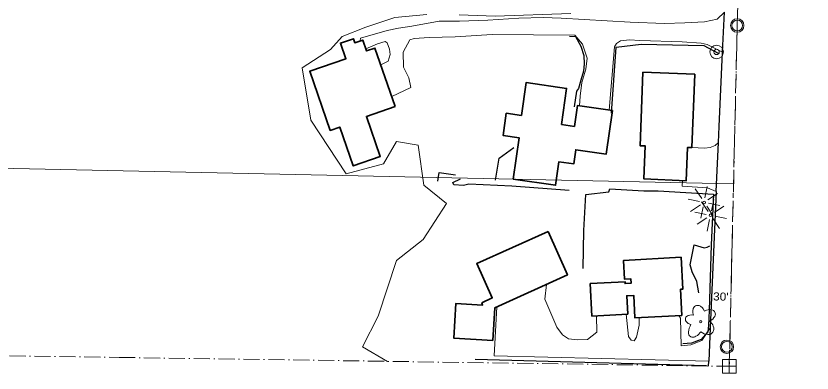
# Model space of a CAD drawing. Extents: x -861682 to -858969, y -1797841 to -1795153.
# Drawn here: x -859566 to -858974, y -1797841 to -1797576 of the extents above; entities that cross this region are included whole.
import ezdxf

# ---------------------------------------------------------------- set-up
doc = ezdxf.new("R2010")
doc.units = 0
doc.header["$LTSCALE"] = 2.4
doc.linetypes.add('DOT_DASHED', pattern=[7.7, 5, -1.2, 0.3, -1.2])
doc.linetypes.add('LONG_DASH_SHORT_DASH', pattern=[9.9, 6, -1.2, 1.5, -1.2])
for name, color, linetype, lineweight in [('10', 7, 'Continuous', 25), ('11', 7, 'Continuous', 13), ('12', 7, 'Continuous', 35), ('14', 7, 'Continuous', 25), ('17', 7, 'Continuous', 13), ('18', 7, 'Continuous', 13), ('30', 7, 'Continuous', 13), ('31', 7, 'Continuous', 13), ('32', 7, 'LONG_DASH_SHORT_DASH', 13), ('36', 7, 'Continuous', 13), ('61', 7, 'Continuous', 13)]:
    doc.layers.add(name, color=color, linetype=linetype, lineweight=lineweight)
doc.layers.add('43', color=7, linetype='Continuous')

msp = doc.modelspace()

# ---------------------------------------------------------------- linework, layer by layer
at = {"layer": '10'}
for p, q in [((-859040.841, -1797602.889), (-859039.445, -1797573.069)), ((-859045.551, -1797706.269), (-859043.943, -1797669.848)), ((-859045.551, -1797706.269), (-859050.013, -1797807.357)), ((-859050.013, -1797807.357), (-859051.105, -1797832.086)), ((-859051.263, -1797835.658), (-859051.105, -1797832.086))]:
    msp.add_line(p, q, dxfattribs=at)
msp.add_lwpolyline([(-859043.943, -1797669.848), (-859043.423, -1797658.051), (-859040.841, -1797602.889)], dxfattribs=at)
at = {"layer": '11'}
for points in [[(-859309.938, -1797594.48), (-859309.62, -1797592.433), (-859289.953, -1797586.603), (-859281.507, -1797585.021), (-859271.667, -1797583.556), (-859251.167, -1797579.721), (-859236.104, -1797579.853), (-859215.218, -1797579.069), (-859192.063, -1797577.66), (-859174.024, -1797577.051), (-859160.73, -1797577.456), (-859109.405, -1797580.619), (-859083.978, -1797581.644), (-859068.807, -1797581.049), (-859054.386, -1797580.217), (-859044.812, -1797578.418), (-859039.445, -1797573.069)], [(-859147.113, -1797642.612), (-859146.722, -1797635.543), (-859145.323, -1797625.243), (-859142.423, -1797615.417), (-859141.468, -1797607.159), (-859144.975, -1797596.843), (-859150.527, -1797590.256), (-859212.015, -1797589.653), (-859239.524, -1797591.399), (-859258.797, -1797591.869), (-859269.741, -1797592.628), (-859273.122, -1797593.726), (-859278.086, -1797602.915), (-859277.739, -1797613.833), (-859273.798, -1797621.755), (-859272.425, -1797628.945), (-859286.527, -1797635.627)], [(-859125.138, -1797645.75), (-859121.079, -1797598.921), (-859119.617, -1797596.398), (-859116.758, -1797594.472), (-859109.954, -1797593.68), (-859102.239, -1797594.124), (-859070.757, -1797595.108), (-859056.83, -1797596.093), (-859052.273, -1797597.107), (-859040.841, -1797602.889)], [(-859294.688, -1797612.104), (-859289.062, -1797609.376), (-859287.679, -1797604.522), (-859288.066, -1797600.452), (-859289.911, -1797595.75), (-859291.415, -1797594.829), (-859297.032, -1797596.522), (-859305.752, -1797600.259)], [(-859063.707, -1797673.43), (-859054.298, -1797673.929), (-859050.097, -1797673.487), (-859046.496, -1797671.924), (-859043.943, -1797669.848)], [(-859070.707, -1797698.023), (-859070.98, -1797702.15), (-859052.078, -1797703.442), (-859045.551, -1797706.269)], [(-859171.524, -1797775.054), (-859172.831, -1797785.961), (-859163.854, -1797806.778), (-859159.648, -1797812.454), (-859155.316, -1797815.589), (-859148.607, -1797816.321), (-859141.261, -1797816.04), (-859134.236, -1797810.611), (-859134.546, -1797798.413)], [(-859208.351, -1797791.81), (-859210.346, -1797828.065), (-859051.105, -1797832.086)], [(-859112.473, -1797797.232), (-859110.759, -1797813.81), (-859108.825, -1797816.542), (-859106.559, -1797817), (-859104.671, -1797814.281), (-859102.725, -1797805.447), (-859102.881, -1797799.818)], [(-859073.379, -1797798.243), (-859072.2, -1797800.255), (-859071.672, -1797820.647), (-859064.559, -1797820.002), (-859056.228, -1797816.66), (-859050.013, -1797807.357)]]:
    msp.add_lwpolyline(points, dxfattribs=at)
at = {"layer": '12'}
for points in [[(-859283.956, -1797643.041), (-859298.988, -1797599.712), (-859305.195, -1797601.865), (-859307.991, -1797593.805), (-859313.914, -1797595.86), (-859314.979, -1797592.791), (-859324.548, -1797596.111), (-859320.548, -1797607.641), (-859347.332, -1797616.933), (-859332.091, -1797660.865), (-859325.078, -1797658.432), (-859315.094, -1797687.21), (-859295.016, -1797680.244), (-859305.348, -1797650.463)], [(-859061.564, -1797619.196), (-859063.712, -1797673.547), (-859066.863, -1797673.422), (-859067.843, -1797698.137), (-859099.293, -1797696.89), (-859098.32, -1797672.349), (-859102.182, -1797672.196), (-859100.022, -1797617.672)], [(-859160.482, -1797656.56), (-859156.642, -1797629.667), (-859186.773, -1797625.365), (-859190.249, -1797649.714), (-859201.45, -1797648.115), (-859203.805, -1797664.611), (-859191.962, -1797666.302), (-859196.345, -1797696.999), (-859164.9, -1797701.489), (-859162.419, -1797684.114), (-859151.41, -1797685.686), (-859149.904, -1797675.141), (-859127.208, -1797678.382), (-859122.6, -1797646.113), (-859148.597, -1797642.401), (-859150.815, -1797657.94)], [(-859170.455, -1797735.959), (-859223.325, -1797759.695), (-859211.923, -1797785.091), (-859219.566, -1797788.668), (-859219.085, -1797790.431), (-859238.911, -1797789.259), (-859240.428, -1797814.91), (-859211.476, -1797816.622), (-859210.036, -1797792.577), (-859156.063, -1797768.019)], [(-859071.07, -1797798.12), (-859105.978, -1797799.984), (-859106.87, -1797783.283), (-859111.975, -1797783.556), (-859111.247, -1797797.167), (-859137.881, -1797798.592), (-859139.168, -1797774.534), (-859113.309, -1797773.151), (-859113.238, -1797774.487), (-859108.853, -1797774.254), (-859109.031, -1797770.903), (-859113.696, -1797771.151), (-859114.433, -1797757.28), (-859071.663, -1797755.008), (-859070.406, -1797778.663), (-859072.103, -1797778.754)]]:
    msp.add_lwpolyline(points, close=True, dxfattribs=at)
at = {"layer": '14'}
msp.add_line((-859052.83, -1797835.473), (-859224.477, -1797830.918), dxfattribs=at)
for points in [[(-859154.593, -1797590.799), (-859149.994, -1797591.146), (-859146.048, -1797598.463), (-859143.848, -1797605.162), (-859143.537, -1797611.489), (-859144.054, -1797616.779), (-859146.133, -1797623.628), (-859147.842, -1797629.64), (-859149.308, -1797631.717), (-859151.052, -1797643.462)], [(-859123.418, -1797647.969), (-859119.926, -1797599.163), (-859101.369, -1797596.865), (-859054.726, -1797597.955), (-859044.172, -1797603.512)], [(-859209.389, -1797697.783), (-859206.852, -1797681.434), (-859195.849, -1797673.51)], [(-859252.288, -1797698.544), (-859251.377, -1797692.037), (-859239.184, -1797693.744)], [(-859154.667, -1797705.493), (-859197.372, -1797702.292), (-859229.2, -1797700.714), (-859233.274, -1797701.673), (-859240.321, -1797701.239), (-859241.111, -1797699.597), (-859235.464, -1797696.886)], [(-859144.48, -1797763.33), (-859143.814, -1797735.156), (-859142.488, -1797708.474), (-859125.346, -1797706.408), (-859124.63, -1797704.094), (-859099.308, -1797705.782), (-859088.664, -1797705.737), (-859047.586, -1797708.204), (-859049.256, -1797745.635), (-859050.728, -1797794.357), (-859051.409, -1797805.403), (-859051.837, -1797810.283), (-859056.649, -1797815.977), (-859063.828, -1797818.72), (-859070.298, -1797819.278)], [(-859058.478, -1797781.31), (-859059.933, -1797772.873), (-859063.443, -1797765.711), (-859064.967, -1797760.455), (-859062.024, -1797745.789), (-859054.446, -1797747.944), (-859052.382, -1797747.53), (-859050.435, -1797746.439)]]:
    msp.add_lwpolyline(points, dxfattribs=at)
at = {"layer": '17'}
for p, q in [((-859056.387, -1797711.387), (-859061.177, -1797704.259)), ((-859053.927, -1797710.927), (-859052.201, -1797702.527)), ((-859057.887, -1797713.587), (-859066.349, -1797711.913)), ((-859051.727, -1797712.327), (-859044.631, -1797707.587)), ((-859049.161, -1797720.461), (-859047.435, -1797712.061)), ((-859057.347, -1797716.087), (-859064.573, -1797720.943)), ((-859056.967, -1797726.047), (-859055.287, -1797717.447)), ((-859051.621, -1797720.921), (-859056.411, -1797713.793)), ((-859052.627, -1797716.987), (-859047.827, -1797724.201)), ((-859051.287, -1797714.847), (-859042.807, -1797716.571)), ((-859046.961, -1797721.861), (-859039.865, -1797717.121)), ((-859053.121, -1797723.121), (-859061.583, -1797721.447)), ((-859046.521, -1797724.381), (-859038.041, -1797726.105)), ((-859052.581, -1797725.621), (-859059.807, -1797730.477)), ((-859052.201, -1797735.581), (-859050.521, -1797726.981)), ((-859047.861, -1797726.521), (-859043.061, -1797733.735))]:
    msp.add_line(p, q, dxfattribs=at)
msp.add_lwpolyline([(-859056.928, -1797810.184), (-859055.886, -1797810.952), (-859054.48, -1797811.674), (-859053.232, -1797812.08), (-859051.86, -1797812.276), (-859050.842, -1797812.226), (-859049.698, -1797811.936), (-859048.766, -1797811.384), (-859048.026, -1797810.596), (-859047.558, -1797809.638), (-859047.348, -1797808.56), (-859047.452, -1797807.364), (-859047.742, -1797806.192), (-859048.228, -1797805.132), (-859048.95, -1797803.988), (-859049.816, -1797803.068), (-859050.498, -1797802.456), (-859049.316, -1797801.74), (-859048.17, -1797800.792), (-859047.25, -1797799.7), (-859046.728, -1797798.844), (-859046.396, -1797798.03), (-859046.25, -1797797.214), (-859046.29, -1797796.452), (-859046.506, -1797795.772), (-859046.764, -1797795.32), (-859047.184, -1797794.846), (-859047.644, -1797794.492), (-859048.21, -1797794.202), (-859049.446, -1797793.874), (-859050.688, -1797793.84), (-859052.734, -1797794.216), (-859054.394, -1797794.854), (-859055.184, -1797793.276), (-859055.838, -1797792.462), (-859056.25, -1797792.06), (-859056.714, -1797791.66), (-859057.316, -1797791.268), (-859058.32, -1797790.836), (-859059.334, -1797790.666), (-859060.222, -1797790.766), (-859061.022, -1797791.1), (-859061.688, -1797791.586), (-859062.248, -1797792.292), (-859062.598, -1797793.048), (-859062.756, -1797793.486), (-859062.924, -1797794.162), (-859062.976, -1797795.324), (-859062.904, -1797796.222), (-859062.692, -1797797.184), (-859062.408, -1797797.99), (-859063.85, -1797797.758), (-859065.208, -1797797.808), (-859066.366, -1797798.094), (-859067.254, -1797798.592), (-859067.694, -1797798.936), (-859068.128, -1797799.502), (-859068.366, -1797800.036), (-859068.49, -1797800.714), (-859068.288, -1797801.818), (-859067.832, -1797802.63), (-859067.208, -1797803.392), (-859066.43, -1797804.008), (-859065.732, -1797804.432), (-859065.068, -1797804.72), (-859064.34, -1797804.958), (-859065.024, -1797806.17), (-859065.646, -1797807.538), (-859066.042, -1797809.04), (-859066.176, -1797810.374), (-859066.166, -1797811.464), (-859065.832, -1797812.482), (-859065.31, -1797813.328), (-859064.752, -1797813.764), (-859064.366, -1797814.01), (-859063.632, -1797814.234), (-859062.838, -1797814.246), (-859062.068, -1797814.122), (-859061.408, -1797813.91), (-859060.664, -1797813.588), (-859059.588, -1797812.908), (-859058.626, -1797812.122), (-859057.67, -1797811.104), (-859056.924, -1797810.194)], dxfattribs=at)
for centre, radius in [((-859054.587, -1797714.287), 1), ((-859049.821, -1797723.821), 1), ((-859057.108, -1797802.772), 0.773)]:
    msp.add_circle(centre, radius, dxfattribs=at)
at = {"layer": '18'}
for points in [[(-859289.615, -1797832.206), (-859308.201, -1797821.475), (-859296.694, -1797798.638), (-859282.842, -1797757.402), (-859263.235, -1797741.691), (-859245.72, -1797714.955), (-859262.726, -1797701.386), (-859266.894, -1797671.816), (-859283.007, -1797669.07), (-859292.635, -1797685.714), (-859320.232, -1797693.031), (-859346.492, -1797653.306), (-859353.108, -1797614.345), (-859331.971, -1797600.704), (-859323.22, -1797591.048), (-859305.656, -1797584.196), (-859284.218, -1797577.042), (-859260.542, -1797574.932)], [(-859236.433, -1797575.112), (-859209.628, -1797575.999), (-859153.532, -1797574.134)]]:
    msp.add_lwpolyline(points, dxfattribs=at)
at = {"layer": '30'}
msp.add_line((-859032.746, -1797700.43), (-859820.703, -1797683.867), dxfattribs=at)
at = {"layer": '31'}
for radius in [5, 2]:
    msp.add_circle((-859045.308, -1797602.637), radius, dxfattribs=at)
at = {"layer": '32'}
msp.add_line((-859002.083, -1796383.657), (-859035.9, -1797835.881), dxfattribs=at)
at = {"layer": '36'}
for centre, radius in [((-859029.979, -1797583.023), 5), ((-859029.979, -1797583.023), 4), ((-859037.662, -1797821.367), 5), ((-859037.662, -1797821.367), 4)]:
    msp.add_circle(centre, radius, dxfattribs=at)
at = {"layer": '61', "linetype": 'DOT_DASHED'}
msp.add_line((-859035.9, -1797835.881), (-858974.429, -1795196.105), dxfattribs=at)
at = {"layer": '61'}
for p, q in [((-859040.9, -1797830.881), (-859030.9, -1797830.881)), ((-859040.9, -1797840.881), (-859040.9, -1797830.881)), ((-859030.9, -1797835.881), (-859040.9, -1797835.881)), ((-859035.9, -1797830.881), (-859035.9, -1797835.881)), ((-859035.9, -1797840.881), (-859035.9, -1797835.881)), ((-859030.9, -1797840.881), (-859030.9, -1797830.881)), ((-859040.9, -1797840.881), (-859030.9, -1797840.881))]:
    msp.add_line(p, q, dxfattribs=at)
at = {"layer": '61', "linetype": 'DOT_DASHED'}
msp.add_lwpolyline([(-861676.699, -1797797.295), (-859488.961, -1797829.261), (-859035.9, -1797835.881)], dxfattribs=at)

# ---------------------------------------------------------------- texts
at = {"layer": '43', "width": 1.1}
msp.add_text("30'", height=6, rotation=358.652, dxfattribs=at).set_placement((-859047.998, -1797786.969))

doc.saveas('drawing.dxf')
